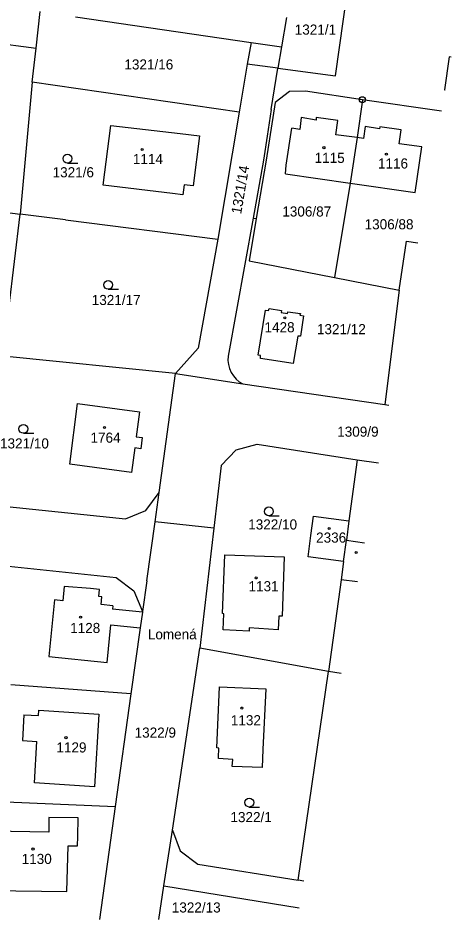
# Model space of a CAD drawing. Extents: x -779596 to -776743, y -1030330 to -1024513.
# Drawn here: x -778691.5 to -778618.7, y -1030130.4 to -1029979.6 of the extents above; entities that cross this region are included whole.
import ezdxf

# ---------------------------------------------------------------- set-up
doc = ezdxf.new("R2010")
doc.units = 0
for name, color, linetype in [('hranice parcel', 7, 'Continuous'), ('hranice vnitřní', 7, 'Continuous'), ('kultura', 7, 'Continuous'), ('Kód', 7, 'Continuous'), ('názvosloví', 7, 'Continuous'), ('č_pacel stav_', 7, 'Continuous'), ('č_parcel poz_', 7, 'Continuous')]:
    doc.layers.add(name, color=color, linetype=linetype)

msp = doc.modelspace()

# ---------------------------------------------------------------- linework, layer by layer
at = {"layer": 'hranice parcel'}
for points in [[(-778638.08, -1029989.37), (-778636.07, -1029975.05)], [(-778688.44, -1029984.74), (-778687.73, -1029978.57)], [(-778681.79, -1029979.44), (-778652.29, -1029983.76)], [(-778646.31, -1029979.6), (-778647.15, -1029984.51)], [(-778696.14, -1029983.71), (-778688.44, -1029984.74)], [(-778689.1, -1029990.46), (-778688.44, -1029984.74)], [(-778652.29, -1029983.76), (-778647.15, -1029984.51)], [(-778647.15, -1029984.51), (-778647.81, -1029988.1)], [(-778618.99, -1029986.2), (-778619.75, -1029991.73)], [(-778618.656, -1029986.248), (-778618.99, -1029986.2)], [(-778652.92, -1029987.43), (-778654.3, -1029995.51)], [(-778647.81, -1029988.1), (-778652.92, -1029987.43)], [(-778648.88, -1029995.06), (-778647.81, -1029988.1)], [(-778647.81, -1029988.1), (-778638.08, -1029989.37)], [(-778689.1, -1029990.46), (-778691.13, -1030012.66)], [(-778654.3, -1029995.51), (-778689.1, -1029990.46)], [(-778645.8, -1029992.06), (-778648.25, -1029993.89)], [(-778643.13, -1029991.99), (-778645.8, -1029992.06)], [(-778633.57, -1029993.42), (-778643.13, -1029991.99)], [(-778619.75, -1029991.73), (-778619.636, -1029991.745)], [(-778648.25, -1029993.89), (-778649.74, -1030003.61)], [(-778633.57, -1029993.42), (-778634.47, -1029999.8)], [(-778620.281, -1029995.362), (-778633.57, -1029993.42)], [(-778654.3, -1029995.51), (-778657.88, -1030016.92)], [(-778648.88, -1029995.06), (-778649.56, -1029999.56)], [(-778643.87, -1029996.39), (-778644.1, -1029998.41)], [(-778641.36, -1029996.85), (-778643.87, -1029996.39)], [(-778641.31, -1029996.43), (-778641.36, -1029996.85)], [(-778637.71, -1029996.94), (-778641.31, -1029996.43)], [(-778638.03, -1029999.32), (-778637.71, -1029996.94)], [(-778677.13, -1030007.78), (-778675.84, -1029997.74)], [(-778675.84, -1029997.74), (-778664.2, -1029999.13)], [(-778646.39, -1030004.44), (-778645.42, -1029998.21)], [(-778644.1, -1029998.41), (-778645.42, -1029998.21)], [(-778633.11, -1029997.95), (-778633.36, -1029999.96)], [(-778630.7, -1029998.31), (-778633.11, -1029997.95)], [(-778630.66, -1029997.96), (-778630.7, -1029998.31)], [(-778627.04, -1029998.49), (-778630.66, -1029997.96)], [(-778627.36, -1030000.86), (-778627.04, -1029998.49)], [(-778664.2, -1029999.13), (-778660.94, -1029999.52)], [(-778660.94, -1029999.52), (-778662.02, -1030007.9)], [(-778649.56, -1029999.56), (-778650.19, -1030003.61)], [(-778634.47, -1029999.8), (-778638.03, -1029999.32)], [(-778634.47, -1029999.8), (-778635.61, -1030007.45)], [(-778633.36, -1029999.96), (-778634.47, -1029999.8)], [(-778623.58, -1030001.36), (-778627.36, -1030000.86)], [(-778624.69, -1030009.03), (-778623.58, -1030001.36)], [(-778650.19, -1030003.61), (-778651.95, -1030013.34)], [(-778649.74, -1030003.61), (-778651.41, -1030013.42)], [(-778646.52, -1030005.87), (-778646.39, -1030004.44)], [(-778646.52, -1030005.87), (-778635.61, -1030007.45)], [(-778635.61, -1030007.45), (-778638.23, -1030023.36)], [(-778635.61, -1030007.45), (-778624.69, -1030009.03)], [(-778721.41, -1030008.78), (-778691.13, -1030012.66)], [(-778665.47, -1030009.21), (-778677.13, -1030007.78)], [(-778663.76, -1030009.42), (-778665.47, -1030009.21)], [(-778663.55, -1030007.73), (-778663.76, -1030009.42)], [(-778662.02, -1030007.9), (-778663.55, -1030007.73)], [(-778693.98, -1030036.57), (-778691.13, -1030012.66)], [(-778687.96, -1030013.07), (-778691.13, -1030012.66)], [(-778683.49, -1030013.64), (-778687.96, -1030013.07)], [(-778683.49, -1030013.64), (-778657.88, -1030016.92)], [(-778651.95, -1030013.34), (-778656.15, -1030036.59)], [(-778651.41, -1030013.42), (-778652.62, -1030020.52)], [(-778651.95, -1030013.34), (-778651.41, -1030013.42)], [(-778657.88, -1030016.92), (-778661.19, -1030035.22)], [(-778627.37, -1030025.46), (-778626.17, -1030017.22)], [(-778626.17, -1030017.22), (-778624.232, -1030017.523)], [(-778652.62, -1030020.52), (-778638.23, -1030023.36)], [(-778638.23, -1030023.36), (-778627.37, -1030025.46)], [(-778627.37, -1030025.46), (-778629.8, -1030044.73)], [(-778645.19, -1030037.8), (-778650.71, -1030036.98), (-778650.69, -1030036.5), (-778651.09, -1030036.41), (-778649.85, -1030028.87), (-778649.34, -1030028.91), (-778649.22, -1030028.57), (-778647.15, -1030028.88), (-778647.22, -1030029.25), (-778646.16, -1030029.4), (-778646.08, -1030029.1), (-778643.98, -1030029.39), (-778644.06, -1030029.71), (-778643.47, -1030029.81), (-778644, -1030033.24), (-778644.4, -1030033.22), (-778645.19, -1030037.8)], [(-778661.19, -1030035.22), (-778664.99, -1030039.52)], [(-778664.99, -1030039.52), (-778693.98, -1030036.57)], [(-778667.75, -1030059.55), (-778664.99, -1030039.52)], [(-778664.99, -1030039.52), (-778653.65, -1030041.27)], [(-778653.65, -1030041.27), (-778629.8, -1030044.73)], [(-778682.78, -1030054.79), (-778681.44, -1030044.58)], [(-778681.44, -1030044.58), (-778671.03, -1030045.95)], [(-778629.8, -1030044.73), (-778629.1, -1030044.831)], [(-778671.03, -1030045.95), (-778671.58, -1030050.16)], [(-778671.58, -1030050.16), (-778670.59, -1030050.29)], [(-778670.59, -1030050.29), (-778670.84, -1030052.17)], [(-778654.77, -1030052.35), (-778651.24, -1030051.43)], [(-778651.24, -1030051.43), (-778634.44, -1030054.05)], [(-778671.83, -1030052.04), (-778672.37, -1030056.16)], [(-778670.84, -1030052.17), (-778671.83, -1030052.04)], [(-778657.29, -1030054.99), (-778654.77, -1030052.35)], [(-778634.44, -1030054.05), (-778635.83, -1030064.34)], [(-778634.44, -1030054.05), (-778630.832, -1030054.546)], [(-778672.37, -1030056.16), (-778682.78, -1030054.79)], [(-778657.29, -1030054.99), (-778658.52, -1030065.53)], [(-778669.96, -1030062.55), (-778667.75, -1030059.55)], [(-778668.43, -1030064.5), (-778667.75, -1030059.55)], [(-778698.79, -1030061.33), (-778673.41, -1030063.98)], [(-778673.41, -1030063.98), (-778669.96, -1030062.55)], [(-778669.81, -1030074.4), (-778668.43, -1030064.5)], [(-778658.52, -1030065.53), (-778668.43, -1030064.5)], [(-778642.21, -1030066.78), (-778641.77, -1030063.51)], [(-778641.77, -1030063.51), (-778635.83, -1030064.34)], [(-778635.83, -1030064.34), (-778636.26, -1030067.58)], [(-778658.52, -1030065.53), (-778660.87, -1030085.73)], [(-778642.69, -1030070.35), (-778642.21, -1030066.78)], [(-778636.74, -1030071.15), (-778636.26, -1030067.58)], [(-778636.26, -1030067.58), (-778633.236, -1030068.028)], [(-778702.7, -1030070.96), (-778674.99, -1030073.86)], [(-778657.08, -1030079.94), (-778656.67, -1030070.02)], [(-778656.67, -1030070.02), (-778646.7, -1030070.39)], [(-778646.7, -1030070.39), (-778647.05, -1030080.38)], [(-778636.74, -1030071.15), (-778642.69, -1030070.35)], [(-778636.74, -1030071.15), (-778637.16, -1030074.24)], [(-778674.99, -1030073.86), (-778671.99, -1030076.1)], [(-778683.68, -1030075.37), (-778683.91, -1030077.77)], [(-778679.29, -1030075.73), (-778683.68, -1030075.37)], [(-778669.81, -1030074.4), (-778670.53, -1030079.55)], [(-778637.16, -1030074.24), (-778639.24, -1030089.68)], [(-778634.409, -1030074.609), (-778637.16, -1030074.24)], [(-778677.76, -1030075.86), (-778679.29, -1030075.73)], [(-778677.88, -1030077.05), (-778677.76, -1030075.86)], [(-778677.38, -1030077.1), (-778677.88, -1030077.05)], [(-778671.99, -1030076.1), (-778670.53, -1030079.55)], [(-778685.35, -1030077.63), (-778686.28, -1030087.17)], [(-778683.91, -1030077.77), (-778685.35, -1030077.63)], [(-778677.51, -1030078.4), (-778677.38, -1030077.1)], [(-778675.52, -1030078.6), (-778677.51, -1030078.4)], [(-778675.52, -1030078.6), (-778675.58, -1030079.2)], [(-778670.55, -1030079.71), (-778675.58, -1030079.2)], [(-778670.55, -1030079.71), (-778670.92, -1030082.33)], [(-778670.53, -1030079.55), (-778670.55, -1030079.71)], [(-778656.88, -1030079.95), (-778657.08, -1030079.94)], [(-778656.99, -1030082.68), (-778656.88, -1030079.95)], [(-778647.6, -1030080.36), (-778647.7, -1030082.65)], [(-778647.05, -1030080.38), (-778647.6, -1030080.36)], [(-778676.49, -1030088.16), (-778675.85, -1030081.84)], [(-778675.85, -1030081.84), (-778670.92, -1030082.33)], [(-778670.92, -1030082.33), (-778672.47, -1030093.42)], [(-778652.63, -1030082.86), (-778656.99, -1030082.68)], [(-778652.59, -1030082.31), (-778652.63, -1030082.86)], [(-778647.7, -1030082.65), (-778652.59, -1030082.31)], [(-778665.51, -1030116.38), (-778660.87, -1030085.73)], [(-778639.24, -1030089.68), (-778660.87, -1030085.73)], [(-778686.28, -1030087.17), (-778676.49, -1030088.16)], [(-778644.39, -1030124.83), (-778639.24, -1030089.68)], [(-778637.151, -1030089.991), (-778639.24, -1030089.68)], [(-778672.47, -1030093.42), (-778692.65, -1030091.93)], [(-778672.47, -1030093.42), (-778675.13, -1030112.43)], [(-778658.06, -1030102.53), (-778657.61, -1030092.27)], [(-778657.61, -1030092.27), (-778649.82, -1030092.62)], [(-778649.82, -1030092.62), (-778650.28, -1030102.83)], [(-778688.03, -1030097.1), (-778687.97, -1030096.2)], [(-778687.97, -1030096.2), (-778677.85, -1030096.84)], [(-778690.46, -1030096.95), (-778690.73, -1030101.31)], [(-778690.46, -1030096.95), (-778688.03, -1030097.1)], [(-778677.85, -1030096.84), (-778678.62, -1030109.07)], [(-778690.73, -1030101.31), (-778688.31, -1030101.47)], [(-778688.72, -1030108.42), (-778688.31, -1030101.47)], [(-778657.68, -1030102.56), (-778658.06, -1030102.53)], [(-778657.69, -1030102.71), (-778657.68, -1030102.56)], [(-778657.76, -1030104.34), (-778657.75, -1030104.04)], [(-778657.75, -1030104.04), (-778657.69, -1030102.71)], [(-778650.28, -1030102.83), (-778650.42, -1030105.83)], [(-778655.37, -1030104.51), (-778657.76, -1030104.34)], [(-778655.44, -1030105.69), (-778655.37, -1030104.51)], [(-778650.42, -1030105.83), (-778655.44, -1030105.69)], [(-778678.62, -1030109.07), (-778688.72, -1030108.42)], [(-778707.91, -1030111), (-778675.13, -1030112.43)], [(-778675.13, -1030112.43), (-778677.79, -1030131.45)], [(-778686.27, -1030114.27), (-778686.3, -1030116.7)], [(-778681.38, -1030114.34), (-778686.27, -1030114.27)], [(-778681.4, -1030117.43), (-778681.38, -1030114.34)], [(-778686.3, -1030116.7), (-778695.88, -1030116.57)], [(-778681.44, -1030119.05), (-778681.4, -1030117.43)], [(-778666.93, -1030125.77), (-778665.51, -1030116.38)], [(-778665.51, -1030116.38), (-778664.18, -1030119.88)], [(-778683.28, -1030126.72), (-778683.05, -1030119.01)], [(-778683.05, -1030119.01), (-778681.9, -1030119.04)], [(-778681.9, -1030119.04), (-778681.44, -1030119.05)], [(-778664.18, -1030119.88), (-778661.24, -1030122.13)], [(-778661.24, -1030122.13), (-778644.39, -1030124.83)], [(-778643.391, -1030124.991), (-778644.39, -1030124.83)], [(-778696.16, -1030126.54), (-778683.28, -1030126.72)], [(-778667.79, -1030131.42), (-778666.93, -1030125.77)], [(-778666.93, -1030125.77), (-778644.193, -1030129.487)]]:
    msp.add_lwpolyline(points, dxfattribs=at)
msp.add_arc((-778651.554, -1030037.143), 4.629, 173.14042, 243.07038, dxfattribs=at)
at = {"layer": 'hranice vnitřní'}
msp.add_lwpolyline([(-778652.29, -1029983.76), (-778652.92, -1029987.43)], dxfattribs=at)
at = {"layer": 'kultura'}
for points in [[(-778683.15, -1030004.09), (-778681.4, -1030004.09)], [(-778676.31, -1030025.34), (-778674.56, -1030025.34)], [(-778690.56, -1030049.58), (-778688.81, -1030049.58)], [(-778649.29, -1030063.48), (-778647.54, -1030063.48)], [(-778652.59, -1030112.49), (-778650.84, -1030112.49)]]:
    msp.add_lwpolyline(points, dxfattribs=at)
for centre, radius in [((-778670.58, -1030001.79), 0.175), ((-778640.03, -1030001.49), 0.175), ((-778683.15, -1030003.34), 0.75), ((-778629.53, -1030002.57), 0.175), ((-778676.31, -1030024.59), 0.75), ((-778646.6, -1030030.15), 0.175), ((-778690.56, -1030048.83), 0.75), ((-778676.92, -1030048.59), 0.175), ((-778649.29, -1030062.73), 0.75), ((-778639.15, -1030065.6), 0.175), ((-778634.62, -1030069.65), 0.175), ((-778651.44, -1030073.93), 0.175), ((-778680.94, -1030080.52), 0.175), ((-778653.83, -1030095.83), 0.175), ((-778683.4, -1030100.82), 0.175), ((-778652.59, -1030111.74), 0.75), ((-778688.94, -1030119.56), 0.175)]:
    msp.add_circle(centre, radius, dxfattribs=at)
at = {"layer": 'Kód'}
for radius in [0.5, 0.032]:
    msp.add_circle((-778633.57, -1029993.42), radius, dxfattribs=at)

# ---------------------------------------------------------------- texts
at = {"layer": 'názvosloví'}
msp.add_text('Lomená', height=1.7, dxfattribs=at).set_placement((-778669.636, -1030084.26))
at = {"layer": 'č_pacel stav_'}
for s, p in [('1114', (-778672.15, -1030004.25)), ('1115', (-778641.6, -1030004.06)), ('1116', (-778630.95, -1030005)), ('1428', (-778650.02, -1030032.57)), ('1764', (-778679.28, -1030051.16)), ('2336', (-778641.346, -1030067.98)), ('1131', (-778652.71, -1030076.17)), ('1128', (-778682.7, -1030083.2)), ('1132', (-778655.68, -1030098.73)), ('1129', (-778685.01, -1030103.31)), ('1130', (-778690.85, -1030122.08))]:
    msp.add_text(s, height=1.7, dxfattribs=at).set_placement(p)
at = {"layer": 'č_parcel poz_'}
for s, p in [('1321/1', (-778644.94, -1029982.46)), ('1321/16', (-778673.58, -1029988.33)), ('1321/6', (-778685.65, -1030006.48)), ('1306/87', (-778647.03, -1030013.08)), ('1306/88', (-778633.19, -1030015.24)), ('1321/17', (-778679.07, -1030027.98)), ('1321/12', (-778641.21, -1030032.89)), ('1309/9', (-778637.8, -1030050.15)), ('1321/10', (-778694.49, -1030052.13)), ('1322/10', (-778652.76, -1030065.77)), ('1322/9', (-778671.86, -1030100.81)), ('1322/1', (-778655.75, -1030115.04)), ('1322/13', (-778665.61, -1030130.25))]:
    msp.add_text(s, height=1.7, dxfattribs=at).set_placement(p)
msp.add_text('1321/14', height=1.7, rotation=80.40064, dxfattribs=at).set_placement((-778653.953, -1030012.76))

doc.saveas('drawing.dxf')
